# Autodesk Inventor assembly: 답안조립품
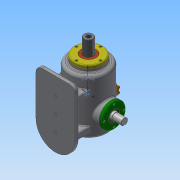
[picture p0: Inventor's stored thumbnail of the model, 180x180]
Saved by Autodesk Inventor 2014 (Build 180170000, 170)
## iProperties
Created: 2018-04
Part Number: 답안조립품
Document SubType Name: Assembly
Designer: net
Author: net
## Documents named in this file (17)
- C:\Users\net\Desktop\380407V1023\답안조립품.iam
- C:\Users\net\Desktop\380407V1023\본체.ipt
- C:\Users\net\Desktop\380407V1023\축 커버-1.ipt
- C:\Users\net\Desktop\380407V1023\축 커버-2.ipt
- C:\Users\net\Desktop\380407V1023\슬라이드 커버.ipt
- C:\Users\net\Desktop\380407V1023\베어링 6205.ipt
- 베어링 6205.ipt
- C:\Users\net\Desktop\380407V1023\편심축.ipt
- C:\Users\net\Desktop\380407V1023\오일실.ipt
- 오일실.ipt
- C:\Users\net\Desktop\380407V1023\슬라이드.ipt
- C:\Users\net\Desktop\380407V1023\부시.ipt
- C:\Users\net\Desktop\380407V1023\볼트 M4.ipt
- 볼트 M4.ipt
- C:\Users\net\Desktop\380407V1023\상부 캡.ipt
- C:\Users\net\Desktop\380407V1023\플레이트.ipt
- C:\Users\net\Desktop\380407V1023\가변스프링.ipt
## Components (2 placed, 2 different names)
1. 플레이트:1
2. 가변스프링:1
